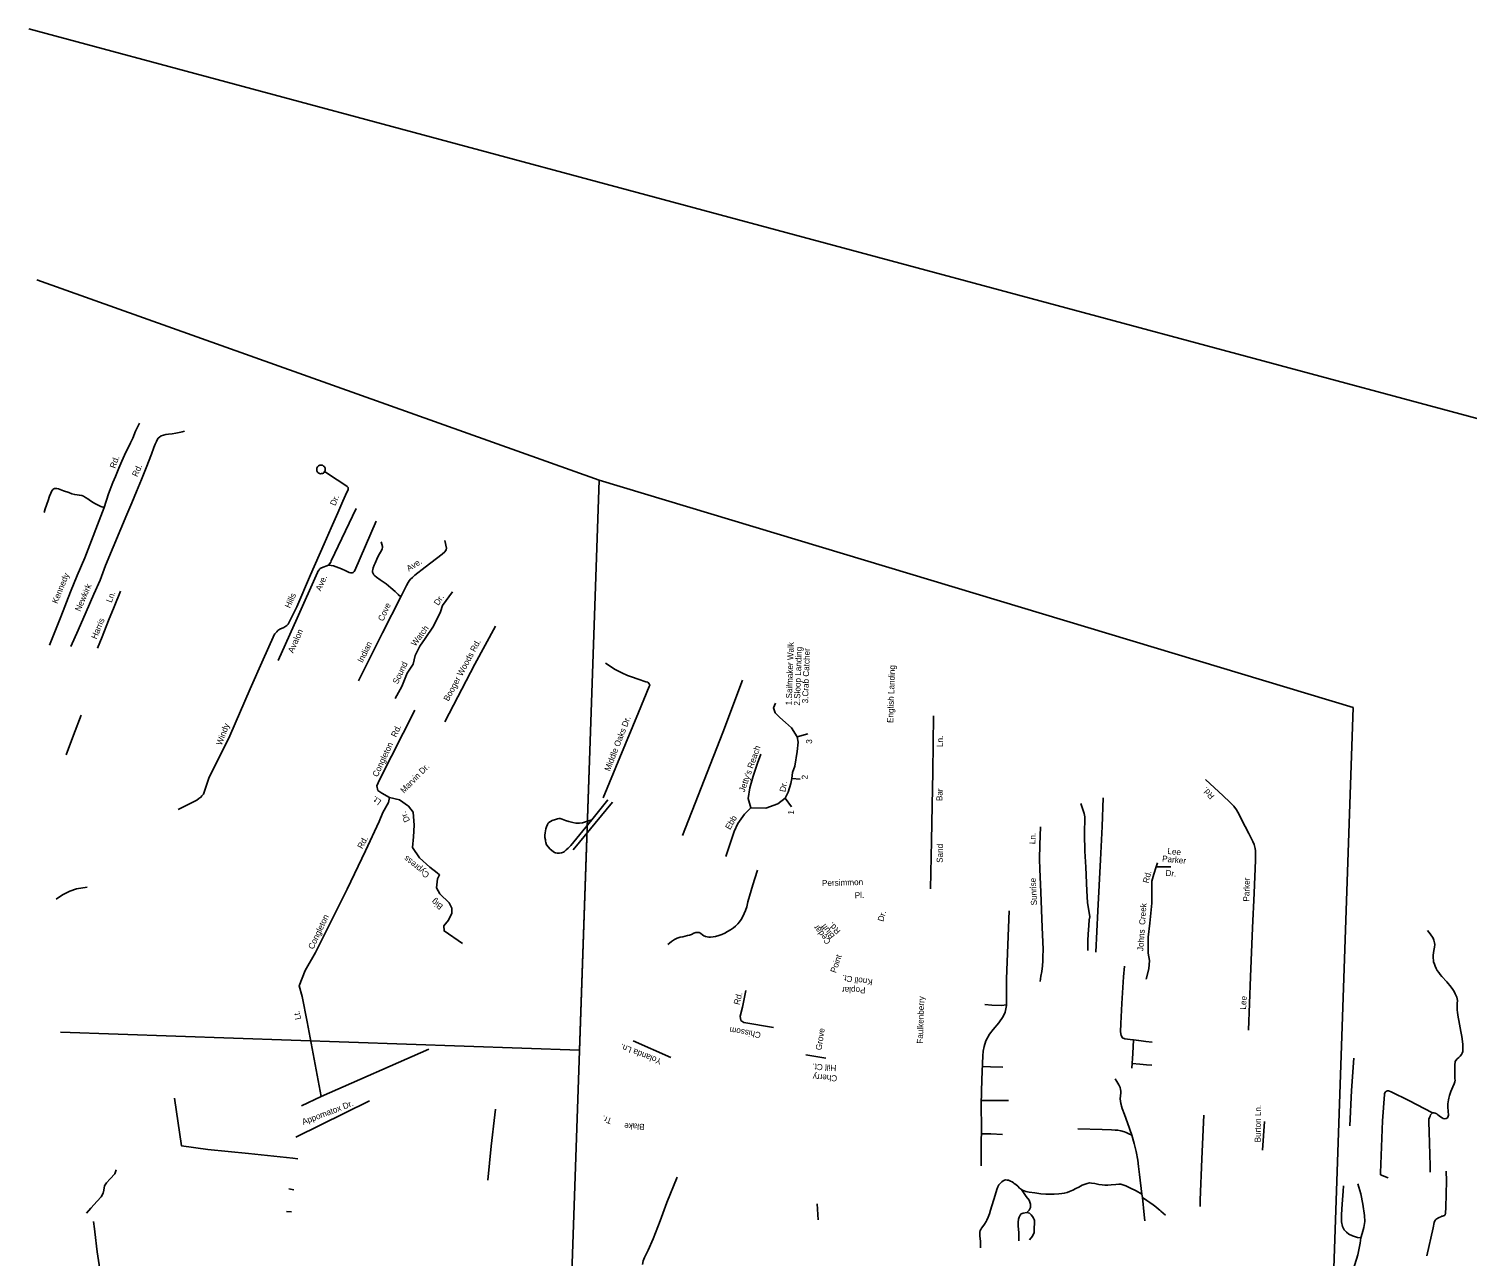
# Model space of a CAD drawing. Extents: x 2308163 to 2335412, y -96774 to 125428.
# Drawn here: x 2308163 to 2323675, y -88852 to -75611 of the extents above; entities that cross this region are included whole.
import ezdxf

# ---------------------------------------------------------------- set-up
doc = ezdxf.new("R2010")
doc.units = 0
for name, color, linetype in [('Old_Level_10', 7, 'Continuous'), ('Old_Level_35', 7, 'Continuous'), ('Old_Level_63', 7, 'Continuous')]:
    doc.layers.add(name, color=color, linetype=linetype)

msp = doc.modelspace()

# ---------------------------------------------------------------- linework, layer by layer
at = {"layer": 'Old_Level_35'}
for p, q in [((2314034, -84467), (2314458, -83955)), ((2314409, -83930), (2314234, -84143)), ((2311065, -87800), (2311012, -87795)), ((2322740, -87951), (2322739, -87974)), ((2323277, -87946), (2323275, -87877)), ((2322739, -87974), (2322823, -88008)), ((2311021, -88135), (2310969, -88126)), ((2320167, -88182), (2320172, -88220)), ((2320193, -88404), (2320172, -88220)), ((2320794, -88316), (2320796, -88247)), ((2308833, -88334), (2308787, -88386)), ((2310996, -88375), (2310944, -88369)), ((2316665, -88286), (2316675, -88459)), ((2320200, -88471), (2320193, -88404)), ((2308862, -88477), (2308871, -88558)), ((2318425, -88693), (2318428, -88761))]:
    msp.add_line(p, q, dxfattribs=at)
for points in [[(2308977, -80774), (2309024, -80626), (2309071, -80507), (2309099, -80441), (2309136, -80352), (2309167, -80277), (2309196, -80212), (2309261, -80078), (2309287, -80026), (2309315, -79951), (2309358, -79864)], [(2308617, -82274), (2308696, -82097), (2308783, -81899), (2308866, -81711), (2308932, -81558), (2308989, -81402), (2309157, -81004), (2309222, -80851), (2309275, -80725), (2309325, -80604), (2309378, -80474), (2309428, -80347), (2309486, -80199), (2309513, -80129), (2309527, -80093), (2309539, -80064), (2309547, -80044), (2309559, -80028), (2309572, -80017), (2309592, -80003), (2309616, -79994), (2309643, -79988), (2309669, -79985), (2309708, -79980), (2309748, -79973), (2309768, -79969), (2309802, -79963), (2309816, -79959), (2309842, -79952)], [(2311354, -80388), (2311347, -80397), (2311340, -80403), (2311332, -80408), (2311321, -80410), (2311310, -80411), (2311300, -80409), (2311292, -80405), (2311284, -80400), (2311278, -80394), (2311273, -80386), (2311270, -80380), (2311269, -80372), (2311268, -80364), (2311268, -80357), (2311270, -80349), (2311274, -80342), (2311278, -80335), (2311283, -80330), (2311289, -80325), (2311296, -80322), (2311302, -80320), (2311312, -80318), (2311320, -80318), (2311330, -80320), (2311337, -80324), (2311343, -80328), (2311348, -80332), (2311352, -80338), (2311356, -80343), (2311358, -80349), (2311360, -80356), (2311360, -80362), (2311360, -80369), (2311359, -80376), (2311357, -80382), (2311354, -80388)], [(2310691, -82415), (2310797, -82174), (2310810, -82150), (2310818, -82138), (2310826, -82126), (2310837, -82115), (2310849, -82103), (2310871, -82089), (2310912, -82068), (2310936, -82055), (2310946, -82047), (2310960, -82033), (2310973, -82012), (2310979, -81997), (2311053, -81848), (2311200, -81501), (2311350, -81168), (2311424, -80995), (2311496, -80831), (2311551, -80708), (2311594, -80610), (2311606, -80586), (2311609, -80573), (2311606, -80560), (2311598, -80550), (2311571, -80530), (2311488, -80478), (2311354, -80388)], [(2308328, -80828), (2308341, -80788), (2308371, -80701), (2308388, -80652), (2308400, -80622), (2308408, -80604), (2308416, -80590), (2308424, -80580), (2308432, -80574), (2308442, -80570), (2308449, -80569), (2308464, -80570), (2308484, -80574), (2308536, -80594), (2308596, -80615), (2308627, -80627), (2308659, -80635), (2308685, -80638), (2308708, -80641), (2308735, -80647), (2308753, -80654), (2308776, -80666), (2308800, -80682), (2308816, -80694), (2308851, -80717), (2308882, -80736), (2308918, -80753), (2308940, -80763), (2308977, -80774)], [(2308385, -82261), (2308508, -81954), (2308614, -81686), (2308684, -81510), (2308767, -81317), (2308977, -80774)], [(2311394, -81396), (2311407, -81382), (2311419, -81364), (2311426, -81350), (2311694, -80785)], [(2311394, -81396), (2311424, -81399), (2311448, -81405), (2311478, -81416), (2311534, -81437), (2311581, -81458), (2311617, -81475), (2311636, -81480), (2311651, -81480), (2311660, -81477), (2311666, -81473), (2311673, -81465), (2311679, -81453), (2311911, -80922)], [(2312177, -81739), (2312147, -81712), (2312116, -81681), (2312067, -81640), (2312016, -81599), (2311953, -81555), (2311914, -81528), (2311896, -81513), (2311886, -81502), (2311880, -81495), (2311873, -81481), (2311871, -81471), (2311869, -81459), (2311872, -81443), (2311878, -81425), (2311889, -81398), (2311898, -81374), (2311916, -81334), (2311940, -81287), (2311962, -81245), (2311975, -81220), (2311979, -81207), (2311979, -81196), (2311963, -81146)], [(2312177, -81739), (2312236, -81618), (2312255, -81583), (2312266, -81566), (2312279, -81550), (2312300, -81530), (2312326, -81504), (2312438, -81417), (2312622, -81277), (2312649, -81254), (2312657, -81243), (2312665, -81230), (2312668, -81214), (2312650, -81132)], [(2310853, -82427), (2311058, -81970), (2311278, -81475), (2311285, -81459), (2311290, -81453), (2311294, -81448), (2311300, -81441), (2311307, -81434), (2311312, -81430), (2311320, -81425), (2311394, -81396)], [(2308905, -82294), (2308953, -82172), (2309024, -81994), (2309083, -81848), (2309152, -81677)], [(2311718, -82646), (2311979, -82128), (2312177, -81739)], [(2312731, -81686), (2312625, -81833), (2312603, -81902), (2312527, -82055), (2312437, -82188), (2312379, -82271), (2312330, -82370), (2312307, -82465), (2312243, -82563), (2312188, -82706), (2312113, -82834)], [(2312650, -83087), (2312973, -82466), (2313196, -82055)], [(2310106, -83696), (2310330, -83237), (2310550, -82730), (2310691, -82415)], [(2314359, -83906), (2314538, -83472), (2314740, -82985), (2314853, -82706), (2314861, -82690), (2314855, -82676), (2314838, -82661), (2314818, -82655), (2314796, -82648), (2314756, -82633), (2314641, -82595), (2314619, -82588), (2314605, -82582), (2314574, -82567), (2314530, -82546), (2314487, -82521), (2314384, -82456)], [(2315214, -84315), (2315647, -83201), (2315861, -82638)], [(2312328, -82962), (2312074, -83457), (2311947, -83714), (2311915, -83777), (2311928, -83827), (2311971, -83858), (2312054, -83905), (2312162, -83929), (2312258, -83996), (2312310, -84062), (2312320, -84201), (2312311, -84329), (2312302, -84442), (2312377, -84554), (2312487, -84656), (2312568, -84717)], [(2315681, -84539), (2315770, -84269), (2315810, -84185), (2315880, -84084), (2315949, -84015), (2316113, -84017), (2316241, -83973), (2316321, -83909), (2316353, -83847), (2316382, -83752), (2316391, -83697), (2316401, -83634), (2316426, -83564), (2316450, -83409), (2316461, -83305), (2316451, -83249), (2316388, -83151), (2316323, -83093), (2316262, -83042), (2316212, -82989), (2316195, -82936), (2316215, -82885)], [(2308727, -83015), (2308647, -83230), (2308566, -83444)], [(2317889, -84890), (2317898, -84370), (2317905, -83990), (2317912, -83626), (2317920, -83024)], [(2316451, -83249), (2316565, -83216)], [(2315949, -84015), (2315920, -83914), (2315938, -83800), (2315976, -83675), (2316022, -83532), (2316059, -83436)], [(2309775, -84032), (2309976, -83931), (2309997, -83915), (2310019, -83900), (2310030, -83884), (2310046, -83868), (2310069, -83804), (2310106, -83696)], [(2316391, -83697), (2316481, -83705)], [(2321316, -86415), (2321340, -85838), (2321361, -85308), (2321378, -84934), (2321391, -84578), (2321391, -84549), (2321391, -84513), (2321391, -84478), (2321390, -84454), (2321386, -84440), (2321377, -84412), (2321362, -84377), (2321320, -84292), (2321279, -84218), (2321201, -84061), (2321187, -84035), (2321157, -83998), (2321114, -83953), (2321043, -83887), (2320854, -83709)], [(2312054, -83905), (2312043, -83957), (2311980, -84065), (2311941, -84162), (2311793, -84480), (2311597, -84891), (2311254, -85576), (2311145, -85769), (2311080, -85936), (2311112, -86051), (2311166, -86325)], [(2316321, -83909), (2316390, -84005)], [(2319671, -85573), (2319693, -85126), (2319720, -84575), (2319737, -84215), (2319751, -83907)], [(2319584, -85555), (2319584, -85461), (2319583, -85423), (2319586, -85399), (2319586, -85377), (2319595, -85283), (2319598, -85223), (2319605, -85191), (2319580, -85037), (2319572, -84911), (2319562, -84656), (2319552, -84484), (2319549, -84300), (2319553, -84112), (2319546, -84077), (2319507, -83967)], [(2314234, -84143), (2314007, -84422), (2313980, -84449), (2313959, -84469), (2313941, -84485), (2313928, -84493), (2313909, -84499), (2313888, -84504), (2313860, -84504), (2313843, -84500), (2313831, -84496), (2313803, -84476), (2313784, -84459), (2313768, -84441), (2313748, -84413), (2313739, -84389), (2313736, -84373), (2313734, -84359), (2313730, -84335), (2313730, -84310), (2313732, -84283), (2313734, -84263), (2313738, -84241), (2313746, -84219), (2313757, -84195), (2313764, -84182), (2313773, -84174), (2313789, -84163), (2313809, -84151), (2313842, -84140), (2313864, -84132), (2313880, -84129), (2313894, -84131), (2313915, -84138), (2313952, -84152), (2313988, -84164), (2314029, -84172), (2314063, -84180), (2314079, -84181), (2314101, -84182), (2314133, -84177), (2314179, -84164), (2314234, -84143)], [(2319092, -85305), (2319079, -84923), (2319067, -84678), (2319064, -84570), (2319067, -84414), (2319074, -84220)], [(2316021, -84687), (2315993, -84778), (2315973, -84844), (2315917, -85028), (2315906, -85082), (2315891, -85124), (2315878, -85155), (2315862, -85186), (2315844, -85218), (2315828, -85244), (2315809, -85268), (2315786, -85291), (2315764, -85311), (2315731, -85332), (2315700, -85350), (2315669, -85366), (2315637, -85380), (2315606, -85393), (2315569, -85403), (2315544, -85407), (2315514, -85409), (2315498, -85409), (2315480, -85408), (2315462, -85403), (2315453, -85399)], [(2320334, -84609), (2320320, -84652), (2320297, -84732), (2320276, -84807), (2320273, -85043), (2320251, -85260), (2320235, -85412), (2320234, -85582), (2320249, -85661), (2320241, -85752), (2320213, -85864)], [(2320320, -84652), (2320480, -84652)], [(2312568, -84717), (2312593, -84739), (2312572, -84782), (2312561, -84877), (2312596, -84941), (2312697, -85039), (2312724, -85099), (2312727, -85153), (2312690, -85226), (2312639, -85288), (2312642, -85343), (2312840, -85478)], [(2308793, -84870), (2308677, -84890), (2308605, -84914), (2308526, -84954), (2308459, -85000)], [(2318736, -85125), (2318727, -85311), (2318708, -85858), (2318706, -86074), (2318706, -86146), (2318693, -86219), (2318671, -86267), (2318623, -86334), (2318564, -86406), (2318522, -86456), (2318483, -86530), (2318466, -86591), (2318455, -86641), (2318453, -86690), (2318441, -86945), (2318433, -87217), (2318436, -87473), (2318435, -87644), (2318433, -87878)], [(2319070, -85889), (2319079, -85831), (2319089, -85779), (2319091, -85749), (2319096, -85723), (2319099, -85663), (2319100, -85621), (2319103, -85544), (2319100, -85459), (2319092, -85305)], [(2315453, -85399), (2315444, -85396), (2315428, -85385), (2315410, -85369), (2315401, -85365), (2315391, -85361), (2315375, -85359), (2315355, -85361), (2315336, -85367), (2315310, -85380), (2315290, -85387), (2315268, -85394), (2315240, -85400), (2315216, -85406), (2315189, -85411), (2315156, -85422), (2315127, -85435), (2315096, -85457), (2315072, -85474), (2315055, -85488)], [(2323301, -87304), (2323308, -87304), (2323316, -87304), (2323330, -87308), (2323347, -87317), (2323359, -87327), (2323389, -87349), (2323404, -87360), (2323417, -87367), (2323434, -87369), (2323448, -87367), (2323461, -87359), (2323467, -87352), (2323471, -87341), (2323473, -87330), (2323465, -87245), (2323466, -87223), (2323466, -87207), (2323473, -87166), (2323478, -87146), (2323484, -87118), (2323491, -87098), (2323499, -87076), (2323510, -87050), (2323522, -87023), (2323535, -86993), (2323542, -86971), (2323544, -86953), (2323543, -86937), (2323542, -86903), (2323541, -86867), (2323542, -86819), (2323543, -86779), (2323545, -86763), (2323547, -86750), (2323552, -86740), (2323568, -86724), (2323586, -86708), (2323601, -86694), (2323613, -86677), (2323622, -86660), (2323627, -86644), (2323629, -86623), (2323629, -86601), (2323628, -86569), (2323625, -86537), (2323616, -86481), (2323605, -86428), (2323591, -86348), (2323573, -86252), (2323569, -86221), (2323567, -86197), (2323566, -86167), (2323568, -86126), (2323569, -86095), (2323567, -86077), (2323562, -86059), (2323555, -86043), (2323547, -86023), (2323534, -85996), (2323520, -85974), (2323501, -85950), (2323454, -85891), (2323401, -85833), (2323384, -85813), (2323368, -85792), (2323351, -85768), (2323339, -85747), (2323328, -85722), (2323321, -85703), (2323313, -85677), (2323310, -85655), (2323308, -85639), (2323308, -85609), (2323311, -85577), (2323320, -85537), (2323324, -85517), (2323325, -85491), (2323322, -85471), (2323315, -85443), (2323307, -85421), (2323274, -85376), (2323247, -85337)], [(2319981, -85724), (2319969, -85839), (2319951, -86124), (2319941, -86342), (2319938, -86431), (2319942, -86472), (2319957, -86496), (2319982, -86508), (2320042, -86515), (2320076, -86516)], [(2315896, -85985), (2315859, -86164), (2315836, -86264), (2315842, -86308), (2315873, -86332), (2316195, -86386)], [(2318706, -86140), (2318654, -86147), (2318549, -86144), (2318475, -86138)], [(2311166, -86325), (2311315, -87128), (2311103, -87231)], [(2314681, -86528), (2315088, -86708)], [(2320076, -86516), (2320068, -86664), (2320057, -86825)], [(2320278, -86544), (2320208, -86534), (2320133, -86526), (2320076, -86516)], [(2311315, -87128), (2312479, -86617)], [(2316757, -86716), (2316544, -86681)], [(2318447, -86807), (2318536, -86808), (2318669, -86813)], [(2320061, -86772), (2320145, -86779), (2320217, -86789), (2320275, -86791)], [(2322410, -87446), (2322429, -87066), (2322452, -86715)], [(2320060, -87547), (2320013, -87412), (2319980, -87325), (2319956, -87257), (2319947, -87232), (2319942, -87214), (2319939, -87204), (2319935, -87178), (2319934, -87154), (2319936, -87122), (2319939, -87090), (2319940, -87072), (2319938, -87053), (2319933, -87032), (2319919, -87002), (2319898, -86967), (2319879, -86939)], [(2311012, -87795), (2310531, -87745), (2310094, -87699), (2309812, -87662), (2309735, -87148)], [(2311043, -87569), (2311838, -87175)], [(2318434, -87173), (2318524, -87171), (2318730, -87171)], [(2323301, -87304), (2323047, -87171), (2322857, -87079), (2322837, -87070), (2322827, -87068), (2322816, -87067), (2322804, -87070), (2322795, -87077), (2322789, -87085), (2322784, -87098), (2322784, -87107), (2322763, -87391), (2322740, -87951)], [(2313195, -87267), (2313189, -87326), (2313150, -87666), (2313113, -88032)], [(2320796, -88247), (2320814, -87800), (2320836, -87332)], [(2323275, -87877), (2323265, -87509), (2323261, -87407), (2323261, -87388), (2323263, -87374), (2323269, -87355), (2323274, -87341), (2323281, -87327), (2323301, -87304)], [(2320060, -87547), (2320025, -87530), (2319999, -87518), (2319979, -87510), (2319941, -87498), (2319907, -87493), (2319879, -87491), (2319841, -87488), (2319737, -87485), (2319478, -87477)], [(2321469, -87708), (2321490, -87398)], [(2318665, -87540), (2318539, -87532), (2318435, -87531)], [(2320167, -88182), (2320140, -87969), (2320132, -87883), (2320122, -87817), (2320104, -87724), (2320084, -87636), (2320060, -87547)], [(2309104, -87921), (2309092, -87963), (2309042, -88018), (2309000, -88062), (2308980, -88092), (2308973, -88140), (2308965, -88172), (2308945, -88210), (2308902, -88258), (2308833, -88334)], [(2323240, -88849), (2323308, -88546), (2323318, -88489), (2323326, -88470), (2323338, -88457), (2323348, -88449), (2323358, -88443), (2323374, -88436), (2323391, -88428), (2323403, -88420), (2323407, -88420), (2323418, -88417), (2323430, -88413), (2323438, -88407), (2323441, -88389), (2323446, -88328), (2323452, -88039), (2323447, -87934)], [(2314782, -88941), (2314789, -88901), (2314802, -88866), (2314844, -88788), (2314897, -88666), (2314973, -88472), (2315044, -88272), (2315156, -88000)], [(2318828, -88098), (2318807, -88080), (2318791, -88069), (2318781, -88061), (2318767, -88050), (2318749, -88041), (2318728, -88033), (2318715, -88030), (2318696, -88029), (2318684, -88032), (2318672, -88038), (2318655, -88050), (2318637, -88067), (2318626, -88081), (2318615, -88104), (2318603, -88132), (2318584, -88192), (2318536, -88357), (2318523, -88396), (2318509, -88432), (2318494, -88464), (2318487, -88478), (2318468, -88507), (2318451, -88531), (2318439, -88551), (2318429, -88564), (2318424, -88576), (2318420, -88592), (2318420, -88606), (2318421, -88632), (2318425, -88693)], [(2320167, -88182), (2320104, -88148), (2320036, -88113), (2319995, -88094), (2319961, -88081), (2319941, -88076), (2319917, -88076), (2319887, -88077), (2319837, -88082), (2319801, -88084), (2319767, -88085), (2319737, -88082), (2319701, -88077), (2319659, -88068), (2319625, -88063), (2319601, -88062), (2319577, -88068), (2319557, -88073), (2319523, -88086), (2319486, -88106), (2319454, -88123), (2319422, -88138), (2319387, -88153), (2319363, -88163), (2319329, -88172), (2319305, -88175), (2319271, -88180), (2319220, -88184), (2319187, -88184), (2319131, -88182), (2319078, -88178), (2319014, -88168), (2318953, -88161), (2318915, -88154), (2318898, -88148), (2318881, -88141), (2318867, -88133), (2318848, -88118), (2318828, -88098)], [(2322527, -88652), (2322493, -88650), (2322437, -88633), (2322400, -88613), (2322374, -88593), (2322348, -88566), (2322331, -88532), (2322321, -88482), (2322320, -88403), (2322328, -88290), (2322336, -88150), (2322342, -88093)], [(2322527, -88652), (2322543, -88607), (2322561, -88543), (2322570, -88479), (2322569, -88411), (2322551, -88290), (2322528, -88180), (2322497, -88071)], [(2318954, -88677), (2318989, -88637), (2319005, -88595), (2319007, -88541), (2319009, -88503), (2319010, -88483), (2319009, -88467), (2319007, -88456), (2318999, -88442), (2318988, -88425), (2318973, -88406), (2318955, -88389), (2318926, -88381), (2318950, -88355), (2318966, -88327), (2318966, -88290), (2318951, -88248), (2318919, -88209), (2318867, -88133)], [(2320360, -88356), (2320347, -88344), (2320317, -88319), (2320288, -88297), (2320253, -88272), (2320219, -88251), (2320172, -88220)], [(2318839, -88686), (2318840, -88596), (2318834, -88528), (2318834, -88485), (2318838, -88451), (2318844, -88429), (2318855, -88409), (2318866, -88394), (2318888, -88386), (2318926, -88381)], [(2320423, -88409), (2320370, -88365), (2320360, -88356)], [(2308871, -88558), (2308875, -88590), (2308902, -88806), (2308935, -89040), (2308954, -89195), (2308952, -89248), (2308933, -89297), (2308885, -89364), (2308835, -89414)], [(2322432, -89098), (2322447, -89000), (2322494, -88836), (2322521, -88712), (2322527, -88652)]]:
    msp.add_lwpolyline(points, dxfattribs=at)
at = {"layer": 'Old_Level_63'}
for p, q in [((2314315, -80480), (2308249, -78319)), ((2322444, -82932), (2314315, -80480))]:
    msp.add_line(p, q, dxfattribs=at)
for points in [[(2335204, -83271), (2332562, -82176), (2308163, -75611)], [(2314315, -80482), (2314103, -86629), (2308504, -86435)], [(2322444, -82932), (2321991, -96076), (2313786, -95817), (2314315, -80480)]]:
    msp.add_lwpolyline(points, dxfattribs=at)

# ---------------------------------------------------------------- texts
at = {"layer": 'Old_Level_10'}
for s, height, rotation, p in [('Rd.', 65.6, 69.6167, (2309095, -80359)), ('Rd.', 65.6, 65.0847, (2309332, -80450)), ('Dr.', 65.6, 67.3169, (2311469, -80762)), ('Ave.', 65.6, 32.0499, (2312262, -81467)), ('Kennedy', 65.6, 67.8467, (2308471, -81818)), ('Ave.', 65.6, 66.0506, (2311312, -81682)), ('Newkirk', 65.6, 66.499, (2308718, -81902)), ('Ln.', 65.6, 69.1108, (2309056, -81807)), ('Hills', 65.6, 65.6411, (2310980, -81867)), ('Dr.', 65.6, 57.3171, (2312581, -81838)), ('Cove', 65.6, 65.514, (2311985, -82008)), ('Harris', 65.6, 67.3307, (2308893, -82201)), ('Watch', 65.6, 53.1139, (2312332, -82277)), ('Avalon', 65.6, 65.8193, (2311014, -82350)), ('Booger Woods Rd.', 65.62, 61.6242, (2312689, -82871)), ('Indian ', 65.6, 63.7995, (2311763, -82455)), ('1.Sailmaker Walk', 65.62, 88.0247, (2316391, -82910)), ('2.Sloop Landing', 65.62, 88.0247, (2316479, -82913)), ('3.Crab Catcher', 65.62, 88.0247, (2316567, -82889)), ('Sound ', 65.6, 64.3347, (2312142, -82687)), ('English Landing', 65.62, 88.0247, (2317485, -83100)), ('Windy', 65.6, 69.4786, (2310243, -83346)), ('Congleton   Rd.', 65.62, 64.9615, (2311925, -83688)), ('Middle Oaks Dr.', 65.62, 68.7633, (2314429, -83626)), ('3', 65.6, 88.0247, (2316610, -83325)), ('Ln.', 65.6, 89.0989, (2318021, -83359)), ("Jetty's Reach", 65.62, 70.5106, (2315881, -83851)), ('Marvin Dr.', 65.6, 45.8234, (2312209, -83863)), ('Dr.', 65.6, 80.239, (2316323, -83848)), ('2', 65.6, 88.0247, (2316564, -83710)), ('Lt.', 65.6, 143.6523, (2311972, -83939)), ('Bar', 65.6, 88.1197, (2318015, -83943)), ('Rd.', 65.6, 132.9634, (2320955, -83885)), ('Dr.', 65.6, 115.5158, (2312276, -84152)), ('1', 65.6, 88.0247, (2316415, -84089)), ('Ebb ', 65.6, 60.3233, (2315726, -84257)), ('Rd.', 65.6, 61.5377, (2311760, -84463)), ('Ln.', 65.6, 88.0624, (2319018, -84408)), ('Cypress', 65.6, 140.9663, (2312490, -84728)), ('Sand', 65.6, 88.9158, (2318019, -84609)), ('Parker', 65.6, 354.2925, (2320383, -84594)), ('Lee', 65.6, 354.2925, (2320440, -84512)), ('Dr.', 65.6, 354.2925, (2320419, -84748)), ('Persimmon ', 65.6, 1.5076, (2316718, -84859)), ('Sunrise', 65.6, 92.8193, (2319037, -85066)), ('Rd.', 65.6, 76.1913, (2320239, -84833)), ('Parker', 65.6, 88.7193, (2321325, -85027)), ('Big', 65.6, 141.4721, (2312636, -85069)), ('Pl.', 65.6, 1.5076, (2317071, -84991)), ('Dr.', 65.6, 74.2787, (2317378, -85247)), ('Johns  Creek ', 65.62, 86.0484, (2320182, -85562)), ('Congleton', 65.6, 64.9413, (2311232, -85547)), ('Cedar ', 65.6, 128.3484, (2316817, -85456)), ('Bluff', 65.6, 128.3484, (2316859, -85396)), ('Rd.', 65.6, 134.7737, (2316923, -85341)), ('Point', 65.6, 71.0018, (2316867, -85801)), ('Poplar', 65.6, 178.5533, (2317187, -85952)), ('Knoll Ct.', 65.6, 171.486, (2317267, -85866)), ('Rd.', 65.6, 75.3776, (2315826, -86145)), ('Faulkenberry', 65.62, 88.1377, (2317805, -86560)), ('Lee', 65.6, 86.8925, (2321290, -86192)), ('Lt. ', 65.6, 101.4483, (2311100, -86294)), ('Chissom', 65.6, 169.6256, (2316062, -86438)), ('Grove ', 65.6, 81.4647, (2316712, -86633)), ('Yolanda Ln.', 65.62, 158.6402, (2314994, -86728)), ('Cherry ', 65.6, 176.1975, (2316883, -86902)), ('Hill Ct.', 65.6, 176.1975, (2316874, -86791)), ('Appomatox Dr.', 65.62, 20.8983, (2311125, -87436)), ('Tr.', 65.6, 159.6034, (2314458, -87368)), ('Burton Ln.', 65.6, 89.2977, (2321448, -87624)), ('Blake', 65.6, 177.5682, (2314804, -87425))]:
    msp.add_text(s, height=height, rotation=rotation, dxfattribs=at).set_placement(p)

doc.saveas('drawing.dxf')
